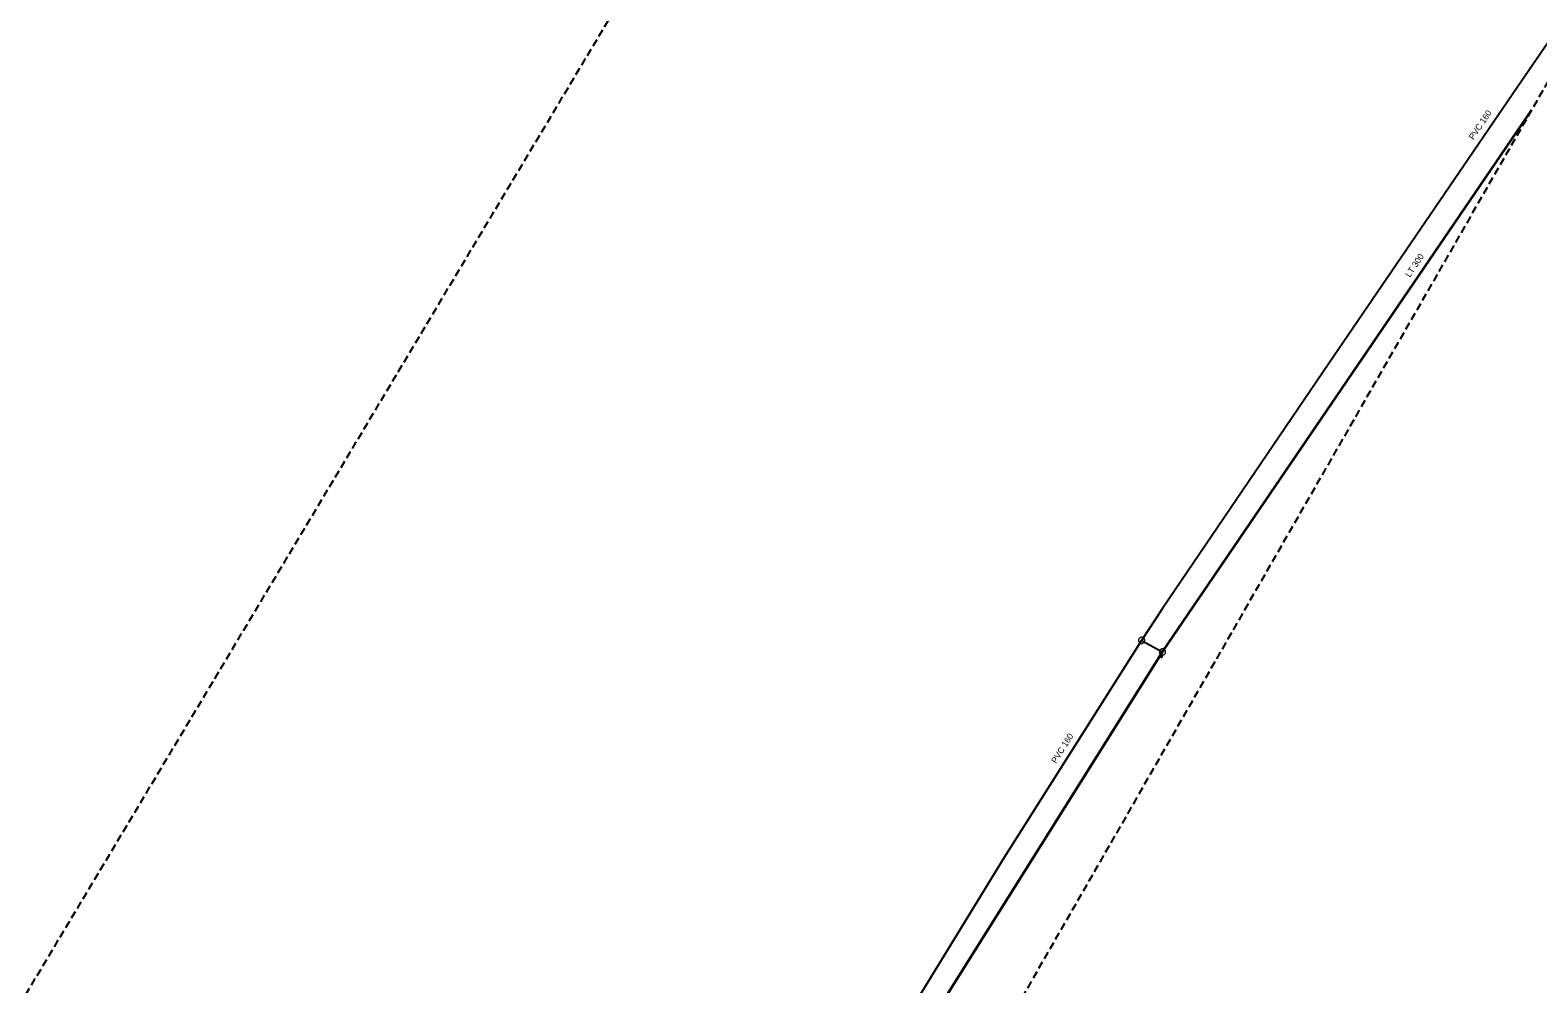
# Model space of a CAD drawing. Extents: x -724358 to -723714, y -973310 to -972026.
# Drawn here: x -724079.6 to -723836.6, y -972681.7 to -972527.9 of the extents above; entities that cross this region are included whole.
import ezdxf

# ---------------------------------------------------------------- set-up
doc = ezdxf.new("R2010")
doc.units = 0
doc.header["$LTSCALE"] = 0.4
doc.linetypes.add('MEDIUM_DASHED', pattern=[4.5, 3, -1.5])
for name, color, linetype, lineweight in [('1', 7, 'Continuous', 13), ('17', 7, 'Continuous', 25), ('23', 7, 'Continuous', 13), ('47', 7, 'Continuous', 13)]:
    doc.layers.add(name, color=color, linetype=linetype, lineweight=lineweight)

msp = doc.modelspace()

# ---------------------------------------------------------------- linework, layer by layer
at = {"layer": '1', "linetype": 'MEDIUM_DASHED', "lineweight": 25}
msp.add_lwpolyline([(-723809.944, -972026.35), (-723713.647, -972034.723), (-723734.581, -972361.295), (-724123.956, -973039.561), (-724241.187, -973309.611), (-724358.418, -973148.418), (-723860.186, -972315.24)], close=True, dxfattribs=at)
at = {"layer": '17', "lineweight": 35}
msp.add_line((-723897.139, -972628.179), (-723837.614, -972540.772), dxfattribs=at)
at = {"layer": '17'}
for points in [[(-723818.009, -972505.129), (-723839.98, -972537.17), (-723870.34, -972581.67), (-723897.149, -972621.19), (-723900.499, -972626.309), (-723897.139, -972628.179)], [(-723900.499, -972626.309), (-723922.64, -972661.32), (-723941.379, -972691.969), (-723954.71, -972713.199), (-723996.149, -972779.55), (-724025.8, -972827.022)]]:
    msp.add_lwpolyline(points, dxfattribs=at)
at = {"layer": '17', "lineweight": 35}
msp.add_lwpolyline([(-724022.349, -972827.559), (-723952.142, -972715.728), (-723897.139, -972628.179)], dxfattribs=at)
at = {"layer": '23'}
for p, q in [((-723897.277, -972629.126), (-723897.207, -972628.666)), ((-723897.403, -972628.856), (-723897.277, -972629.126)), ((-723897.094, -972628.926), (-723897.391, -972628.88)), ((-723897.115, -972628.951), (-723897.379, -972628.911)), ((-723897.138, -972628.971), (-723897.363, -972628.937)), ((-723897.158, -972628.991), (-723897.352, -972628.963)), ((-723897.176, -972629.013), (-723897.341, -972628.989)), ((-723897.196, -972629.038), (-723897.329, -972629.017)), ((-723897.216, -972629.059), (-723897.316, -972629.045)), ((-723897.238, -972629.08), (-723897.301, -972629.07)), ((-723897.257, -972629.104), (-723897.289, -972629.099)), ((-723897.077, -972628.905), (-723897.24, -972628.88))]:
    msp.add_line(p, q, dxfattribs=at)
msp.add_lwpolyline([(-723897.634, -972628.105), (-723897.637, -972628.157), (-723897.638, -972628.208), (-723897.633, -972628.261), (-723897.622, -972628.312), (-723897.605, -972628.362), (-723897.582, -972628.409), (-723897.555, -972628.454), (-723897.524, -972628.497), (-723897.49, -972628.536), (-723897.451, -972628.57), (-723897.408, -972628.601), (-723897.361, -972628.625), (-723897.315, -972628.647), (-723897.264, -972628.663), (-723897.212, -972628.673), (-723897.161, -972628.677), (-723897.109, -972628.678), (-723897.056, -972628.672), (-723897.006, -972628.661), (-723896.956, -972628.644), (-723896.908, -972628.621), (-723896.863, -972628.596), (-723896.82, -972628.564), (-723896.783, -972628.529), (-723896.748, -972628.49), (-723896.717, -972628.447), (-723896.692, -972628.402), (-723896.671, -972628.354), (-723896.655, -972628.304), (-723896.644, -972628.252), (-723896.641, -972628.201), (-723896.64, -972628.148), (-723896.645, -972628.096), (-723896.656, -972628.046), (-723896.674, -972627.996), (-723896.695, -972627.948), (-723896.722, -972627.902), (-723896.753, -972627.861), (-723896.788, -972627.822), (-723896.827, -972627.787), (-723896.87, -972627.756), (-723896.915, -972627.731), (-723896.964, -972627.71), (-723897.015, -972627.695), (-723897.066, -972627.684), (-723897.118, -972627.68), (-723897.169, -972627.68), (-723897.222, -972627.685), (-723897.273, -972627.696), (-723897.323, -972627.713), (-723897.37, -972627.735), (-723897.413, -972627.761), (-723897.455, -972627.792), (-723897.496, -972627.828), (-723897.53, -972627.867), (-723897.561, -972627.91), (-723897.586, -972627.955), (-723897.607, -972628.004), (-723897.624, -972628.054)], close=True, dxfattribs=at)
msp.add_lwpolyline([(-723897.277, -972629.126), (-723897.077, -972628.905), (-723897.403, -972628.856)], dxfattribs=at)
at = {"layer": '47'}
for points in [[(-723900.186, -972626.699), (-723900.147, -972626.664), (-723900.112, -972626.625), (-723900.081, -972626.583), (-723900.054, -972626.538), (-723900.033, -972626.49), (-723900.017, -972626.44), (-723900.006, -972626.389), (-723900, -972626.337), (-723899.999, -972626.286), (-723900.004, -972626.233), (-723900.015, -972626.181), (-723900.031, -972626.132), (-723900.052, -972626.084), (-723900.078, -972626.039), (-723900.108, -972625.996), (-723900.143, -972625.957), (-723900.182, -972625.922), (-723900.224, -972625.891), (-723900.269, -972625.864), (-723900.317, -972625.843), (-723900.367, -972625.827), (-723900.418, -972625.815), (-723900.47, -972625.809), (-723900.522, -972625.809), (-723900.574, -972625.814), (-723900.626, -972625.825), (-723900.676, -972625.841), (-723900.723, -972625.862), (-723900.768, -972625.888), (-723900.811, -972625.918), (-723900.85, -972625.953), (-723900.885, -972625.992), (-723900.917, -972626.034), (-723900.943, -972626.079), (-723900.964, -972626.127), (-723900.981, -972626.176), (-723900.992, -972626.227), (-723900.998, -972626.279), (-723900.998, -972626.332), (-723900.993, -972626.384), (-723900.982, -972626.436), (-723900.967, -972626.485), (-723900.945, -972626.533), (-723900.919, -972626.578), (-723900.889, -972626.621), (-723900.854, -972626.66), (-723900.815, -972626.695), (-723900.774, -972626.726), (-723900.728, -972626.753), (-723900.68, -972626.774), (-723900.631, -972626.791), (-723900.58, -972626.802), (-723900.528, -972626.807), (-723900.476, -972626.808), (-723900.423, -972626.803), (-723900.371, -972626.792), (-723900.323, -972626.776), (-723900.274, -972626.755), (-723900.229, -972626.729)], [(-723900.447, -972626.373), (-723900.44, -972626.367), (-723900.435, -972626.36), (-723900.43, -972626.354), (-723900.426, -972626.346), (-723900.422, -972626.338), (-723900.42, -972626.33), (-723900.417, -972626.322), (-723900.417, -972626.313), (-723900.417, -972626.305), (-723900.417, -972626.296), (-723900.419, -972626.287), (-723900.422, -972626.279), (-723900.425, -972626.272), (-723900.429, -972626.264), (-723900.434, -972626.257), (-723900.44, -972626.25), (-723900.447, -972626.245), (-723900.453, -972626.24), (-723900.461, -972626.236), (-723900.469, -972626.232), (-723900.477, -972626.23), (-723900.485, -972626.227), (-723900.494, -972626.227), (-723900.503, -972626.226), (-723900.511, -972626.227), (-723900.52, -972626.229), (-723900.528, -972626.232), (-723900.535, -972626.235), (-723900.543, -972626.239), (-723900.55, -972626.244), (-723900.557, -972626.25), (-723900.562, -972626.257), (-723900.567, -972626.263), (-723900.571, -972626.271), (-723900.575, -972626.279), (-723900.578, -972626.286), (-723900.58, -972626.295), (-723900.58, -972626.304), (-723900.581, -972626.313), (-723900.58, -972626.321), (-723900.578, -972626.33), (-723900.575, -972626.338), (-723900.572, -972626.345), (-723900.568, -972626.353), (-723900.563, -972626.36), (-723900.557, -972626.367), (-723900.55, -972626.372), (-723900.544, -972626.377), (-723900.536, -972626.381), (-723900.528, -972626.385), (-723900.521, -972626.388), (-723900.512, -972626.39), (-723900.503, -972626.39), (-723900.495, -972626.39), (-723900.486, -972626.39), (-723900.477, -972626.388), (-723900.469, -972626.385), (-723900.462, -972626.382), (-723900.454, -972626.378)]]:
    msp.add_lwpolyline(points, close=True, dxfattribs=at)

# ---------------------------------------------------------------- texts
at = {"layer": '1'}
for s, rotation, p in [('PVC 160 ', 56, (-723847.006, -972545.702)), ('LT 300', 56, (-723857.256, -972567.864)), ('PVC 160 ', 58, (-723914.273, -972646.245))]:
    msp.add_text(s, height=1, rotation=rotation, dxfattribs=at).set_placement(p)

doc.saveas('drawing.dxf')
